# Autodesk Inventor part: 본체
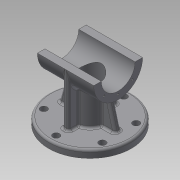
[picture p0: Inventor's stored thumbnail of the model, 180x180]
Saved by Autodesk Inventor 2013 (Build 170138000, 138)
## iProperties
Created: 2015-12
Part Number: 본체
Material: 알루미늄 6061
Document SubType Name: Modeling
Designer: mduedu
Density: 2.71 g/cm^3
Mass: 517.26 g
Surface Area: 494.061 cm^2
Volume: 190.871 cm^3
Author: mduedu
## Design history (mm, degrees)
sketch "스케치1"
  geometry: C1 r 55 at (0, 0); 1 further point
  constraints: 1 centre point, 1 coincident
  dimensions: "d124" = 110 diameter of C1
extrude "돌출1" new body sketch "스케치1" distance "d3" = 10; taper "d4" = 0 deg
sketch "스케치2"
  geometry: C1 r 32.5 at (80, 0); 1 further point
  constraints: 1 centre point, 1 horizontal alignment
  dimensions: "d5" = 65 diameter of C1; "d125" = 80 distance of C1.centre point (0, 0)
extrude "돌출2" join sketch "스케치2" stored distance "d7" = 75; taper "d8" = 0 deg
sketch "스케치3"
  geometry: C1 r 20 at (0, 0); 1 further point
  constraints: 1 centre point, 1 coincident
  dimensions: "d154" = 40 diameter of C1
extrude "돌출3" new body sketch "스케치3" stored distance "d12" = 75; taper "d13" = 0 deg
feature "결합1"
  node "솔리드2"
sketch "스케치19"
  geometry: L1 (0, 55)-(10, 55) reference; L2 (10, 55)-(10, 20) reference; L3 (10, 20)-(54.383, 20) reference; L4 (54.383, -20)-(10, -20) reference; L5 (10, -20)-(10, -55) reference; L6 (10, -55)-(0, -55) reference; L7 (0, -55)-(0, 55) reference; L8 (10, -32.5)-(80, -32.5); A1 r 32.5 centre (80, 0) between (54.383, -20) and (54.383, 20) reference; 1 further point
  constraints: 2 end point, 1 horizontal, 1 point on circle, 1 point on line, 1 tangent
feature "리브3" sketch "스케치19" dims "d161" = 1, "d162" = 8, "d163" = 0, "d164" = 0, "d165" = 1, "d166" = 1
sketch "스케치20"
  geometry: L1 (-37.5, 47.5)-(-37.5, 112.5) reference; L2 (-37.5, 112.5)-(37.5, 112.5) reference; L3 (37.5, 112.5)-(37.5, 47.5) reference; L4 (37.5, 47.5)-(20, 47.5) reference; L5 (20, 47.5)-(20, 10) reference; L6 (20, 10)-(55, 10) reference; L7 (55, 10)-(55, 0) reference; L8 (55, 0)-(-55, 0) reference; L9 (-55, 0)-(-55, 10) reference; L10 (-55, 10)-(-20, 10) reference; L11 (-20, 10)-(-20, 47.5) reference; L12 (-20, 47.5)-(-37.5, 47.5) reference; L13 (27.5, 47.5)-(37.548, 10); 1 further point
  constraints: 2 end point, 2 point on line
  dimensions: "d167" = 10 distance from line of L13.start L3; "d168" = 105 deg angle of L13 L6
feature "리브4" sketch "스케치20" dims "d169" = 1, "d170" = 8, "d171" = 0, "d172" = 0, "d173" = 1, "d174" = 1
fillet "모깎기14" dims "d175" = 3
fillet "모깎기15" dims "d176" = 3
fillet "모깎기7" dims "d41" = 3
hole "구멍2" diameter "d44" = 45; stored, may be unused: countersink angle "d48" = 90 deg, drill point angle "d50" = 118 deg; dims "d42" = 10, "d43" = 10, "d45" = 6, "d46" = 4, "d47" = 2, "d49" = 8
sketch "스케치7" dims "d52" = 26.5
  geometry: L1 (0, 0)-(32.5, 0); L2 (0, 0)-(0, 32.5); A1 r 32.5 centre (0, 0) between (32.5, 0) and (0, 32.5) reference; 3 further points
  constraints: 4 end point, 2 point on circle, 1 coincident, 1 horizontal, 1 point on line, 1 vertical alignment, 2 other
  dimensions: "d51" = 90 deg angle of L2 L1
hole "구멍3" sketch "스케치7" at (0, 26.5) diameter "d54" = 2.459; stored, may be unused: countersink angle "d58" = 90 deg, drill point angle "d60" = 118 deg; dims "d55" = 8, "d56" = 4, "d57" = 2, "d59" = 10
sketch "스케치9"
  geometry: L1 (-75, 82.5)-(75, 82.5); L2 (75, 82.5)-(75, 0); L3 (75, 0)-(-75, 0); L4 (-75, 0)-(-75, 82.5); C1 r 32.5 at (0, 0) reference; 2 further points
  constraints: 8 end point, 2 parallel, 1 coincident, 1 horizontal, 1 midpoint, 1 perpendicular
  dimensions: "d71" = 50 distance edge to line of C1 L1; "d116" = 150 distance between parallel lines of L2 L4
extrude "돌출5" cut sketch "스케치9" stored distance "d73" = 0; taper "d74" = 0 deg
node "작업 평면1"
sketch "스케치10"
  geometry: C1 r 15 at (0, 0); 1 further point
  constraints: 1 centre point, 1 coincident
  dimensions: "d156" = 30 diameter of C1
extrude "돌출6" cut sketch "스케치10" stored distance "d78" = 50; taper "d79" = 0 deg
sketch "스케치11"
  geometry: 2 further points
  constraints: 1 coincident
hole "구멍4" sketch "스케치11" at (0, 0) diameter "d81" = 12; stored, may be unused: countersink angle "d85" = 90 deg, drill point angle "d87" = 118 deg; dims "d82" = 8, "d83" = 30, "d84" = 10, "d86" = 10
sketch "스케치12"
  geometry: C1 r 10 at (0, 0); 1 further point
  constraints: 1 centre point, 1 coincident
  dimensions: "d88" = 20 diameter of C1
extrude "돌출7" cut sketch "스케치12" distance "d89" = 10; taper "d90" = 0 deg
chamfer "모따기1" distance "d91" = 1; stored, may be unused: second distance "d92" = 2, angle "d93" = 45 deg
sketch "스케치18" dims "d141" = 90
  geometry: C1 r 52 at (0, 0) reference; 2 further points
  constraints: 2 vertical alignment, 1 coincident, 2 other
hole "구멍8" sketch "스케치18" at (0, 45) diameter "d142" = 9; stored, may be unused: countersink angle "d146" = 90 deg, drill point angle "d148" = 118 deg; dims "d143" = 6, "d144" = 4, "d145" = 2, "d147" = 8
node "솔리드1"
mirror "대칭8"
mirror "대칭9"
pattern_circular "원형 패턴1" dims angle "d62" = 360 deg
mirror "대칭3"
pattern_circular "원형 패턴2" dims angle "d150" = 360 deg
node "절단 모서리 투영1"
node "절단 모서리 투영2"
